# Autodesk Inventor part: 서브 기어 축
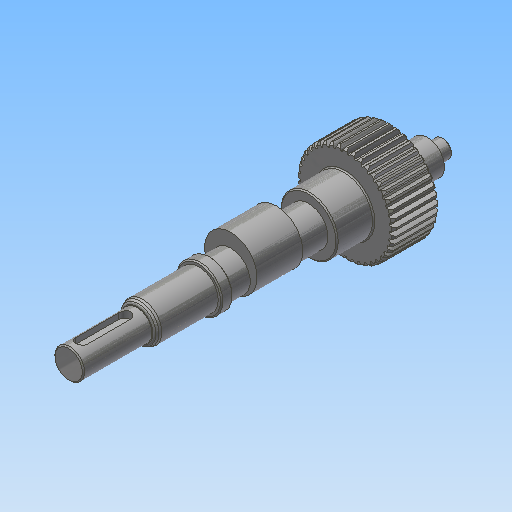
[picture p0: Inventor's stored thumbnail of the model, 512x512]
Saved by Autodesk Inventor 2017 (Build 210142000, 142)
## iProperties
Created: 2018-12
Part Number: 서브 기어 축
Material: 강철, 연강
Document SubType Name: Modeling
Designer: mduedu
Categories: <?xml version="1.0" encoding="UTF-16"?> <MemberInstance><Categories><FamilyTemplate><FamilyTemplateParameter ValueType="xs:double" Id="1" ObjectReferenceKey="da
Density: 1 g/cm^3
Appearance: 강철
Author: mduedu
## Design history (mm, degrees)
sketch "Sketch1"
  geometry: C1 r 21.3 at (0, 0)
  constraints: 1 centre point
  dimensions: "d0" = 42.6 diameter of C1 (= da_da)
extrude "Extrusion1" new body sketch "Sketch1" distance "d1" = 20 (= da_b); taper "d2" = 0 deg
workplane "Work Plane2"
sketch "Sketch2"
  geometry: C1 r 21.3 at (0, 0) reference; C2 r 20.5 at (0, 0)
  constraints: 1 centre point, 1 coincident
  dimensions: "d3" = 41 diameter of C2 (= da_dw)
feature "피치 지름" sketch "Sketch2" dims "d4" = 10, "d5" = 0
workplane "Work Plane8"
workplane "Work Plane9"
chamfer "모따기1" distance "d49" = 1; stored, may be unused: second distance "d50" = 2, angle "d51" = 45 deg
sketch "스케치3"
  geometry: C1 r 12.5 at (0, 0); 1 further point
  constraints: 1 centre point, 1 coincident
  dimensions: "d52" = 25 diameter of C1
extrude "돌출2" join sketch "스케치3" distance "d53" = 16; taper "d54" = 0 deg
sketch "스케치4"
  geometry: C1 r 8.5 at (0, 0); 1 further point
  constraints: 1 centre point, 1 coincident
  dimensions: "d55" = 17 diameter of C1
extrude "돌출3" join sketch "스케치4" distance "d56" = 105; taper "d57" = 0 deg
sketch "스케치5"
  geometry: C1 r 7.5 at (0, 0); 1 further point
  constraints: 1 centre point, 1 coincident
  dimensions: "d58" = 15 diameter of C1
extrude "돌출4" join sketch "스케치5" distance "d59" = 16; taper "d60" = 0 deg
sketch "스케치6"
  geometry: C1 r 4 at (0, 0); 1 further point
  constraints: 1 centre point, 1 coincident
  dimensions: "d61" = 8 diameter of C1
extrude "돌출5" join sketch "스케치6" distance "d62" = 7; taper "d63" = 0 deg
fillet "모깎기1" dims "d67" = 0.5
feature "스퍼 기어" dims "da_b" = 20, "da_d" = 41, "da_aw" = 31, "da_da" = 42.6, "da_df" = 39.086, "da_dw" = 41, angle "da_beta" = 0 deg, "da_lefttooth" = 0, "da_righttooth" = 0
node "작업 평면11"
sketch "스케치7"
  geometry: C1 r 11.5 at (0, 3); C2 r 8.5 at (0, 0) reference; 1 further point
  constraints: 1 centre point, 1 tangent, 1 vertical alignment
  dimensions: "d69" = 3 distance of point (0, 0) C1.centre; "d70" = 23 diameter of C1 (derived)
extrude "돌출6" join sketch "스케치7" stored distance "d71" = 20; taper "d72" = 0 deg
node "작업 평면12"
sketch "스케치8"
  geometry: C1 r 12.5 at (0, 0) reference; C2 r 10 at (0, 0); 1 further point
  constraints: 1 centre point, 1 coincident
  dimensions: "d110" = 20 diameter of C2
extrude "돌출7" join sketch "스케치8" distance "d74" = 5; taper "d75" = 0 deg
sketch "스케치14"
  geometry: L1 (-11.5, 111)-(-6.5, 111); L2 (-6.5, 111)-(-6.5, 141); L3 (-6.5, 141)-(-11.5, 141); L4 (-11.5, 141)-(-11.5, 111); L5 (8.5, 141)-(-8.5, 141) reference; L6 (0, 0)-(0, 141)
  constraints: 10 end point, 2 parallel, 1 collinear, 1 horizontal, 1 midpoint, 1 perpendicular
  dimensions: "d92" = 30 distance between parallel lines of L1 L5; "d93" = 13 diameter of L2 L6; "d95" = 5 distance of L2.end L3.end
revolve "회전2" sketch "스케치14" stored, may be unused: angle "d96" = 90 deg
chamfer "모따기4" distance "d97" = 0.5; stored, may be unused: second distance "d98" = 2, angle "d99" = 45 deg
revolve "회전1" stored, may be unused: angle "d82" = 90 deg
sketch "스케치10"
  geometry: L1 (-6.5, 117.5)-(-5, 116) reference; L2 (-6.5, 114.5)-(-5, 116) reference; 2 further points
  constraints: 1 coincident
node "작업점1"
node "작업 평면13"
sketch "스케치11"
  geometry: L1 (-2.5, 9.5)-(-2.5, -9.5); L2 (2.5, -9.5)-(2.5, 9.5); L3 (-6, 15)-(6, 15) reference; A1 r 2.5 centre (0, 9.5) between (2.5, 9.5) and (-2.5, 9.5); A2 r 2.5 centre (0, -9.5) between (-2.5, -9.5) and (2.5, -9.5); 1 further point
  constraints: 4 end point, 4 point on circle, 4 tangent, 2 centre point, 2 vertical alignment, 1 parallel
  dimensions: "d84" = 24 dimension on A2 A1; "d85" = 5 distance between parallel lines of L1 L2; "d108" = 3 distance edge to line of A1 L3
extrude "돌출8" cut sketch "스케치11" distance "d86" = 3; taper "d87" = 0 deg
sketch "스케치12" dims "d88" = 32
  geometry: C1 r 0.5 at (0, -16); 2 further points
  constraints: 2 vertical alignment, 1 centre point, 1 coincident, 2 other
  dimensions: "d89" = 1 diameter of C1
extrude "돌출9" join sketch "스케치12" distance "d90" = 0.3; taper "d91" = 0 deg
sketch "스케치13"
  geometry: C1 r 11.5 at (0, 3) reference; 1 further point
  node "절단 모서리 투영1"
sketch "스케치15"
  geometry: L1 (-8.5, 109.181)-(-7.45, 111); L2 (-8.5, 111)-(8.5, 111) reference; L3 (-8.5, 84)-(-8.5, 111) reference; L4 (0, 0)-(0, 111); L5 (-7.45, 111)-(-8.5, 111); L6 (-8.5, 109.181)-(-8.5, 111)
  constraints: 8 end point, 2 collinear, 2 point on line, 1 midpoint
  dimensions: "d103" = 14.9 diameter of L1.end L4; "d104" = 30 deg angle of L3 L1
revolve "회전3" sketch "스케치15" stored, may be unused: angle "d105" = 90 deg
fillet "모깎기2" dims "d106" = 2
fillet "모깎기3" dims "d107" = 1
chamfer "모따기5" distance "d112" = 0.5; stored, may be unused: second distance "d113" = 2, angle "d114" = 45 deg
body "Solid1"
body "Srf1"
node "투영된 루프1"
sketch "스케치9"
  geometry: L1 (0, 138.97)-(0, 0); L2 (-6.5, 116)-(0, 116); L3 (-6.5, 116)-(-6.5, 114.5); L4 (-6.5, 114.5)-(-5, 116); L5 (-5, 116)-(-6.5, 116); L6 (-6, 141)-(6, 141) reference
  constraints: 10 end point, 2 point on line, 1 collinear, 1 vertical
  dimensions: "d80" = 3 diameter of L3.end L2; "d100" = 25 distance between parallel lines of L6 L2; "d101" = 6.5 distance between parallel lines of L1 L3; "d102" = 45 deg angle of L4 L3
other parameters: "d16" = 31 (= da_aw), "d17" = 0, "d34" = 0.76624 (computed from da_z), "d39" = 0, "d41" = 0, "d43" = 31 (= da_aw), "d46" = 31 (= da_aw), "d47" = 0, "d48" = 0
